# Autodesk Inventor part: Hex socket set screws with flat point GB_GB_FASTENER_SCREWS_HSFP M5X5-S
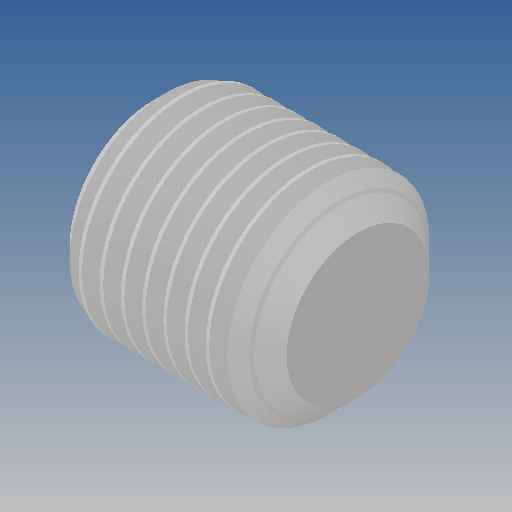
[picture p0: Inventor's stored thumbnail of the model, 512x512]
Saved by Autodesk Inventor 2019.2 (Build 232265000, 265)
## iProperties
Created: 2013-09
Part Number: Hex socket set screws with flat point GB_GB_FASTENER_SCREWS_HSFP M5X5-S
Material: Ogólny
Document SubType Name: Modeling
Designer: CADENGINEERING4
Density: 1 g/cm^3
Appearance: Domyślna
Author: CADENGINEERING4
Revision Number: ÈÎºÎ
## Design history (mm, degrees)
feature "LPattern10"
node "Bryła1"
